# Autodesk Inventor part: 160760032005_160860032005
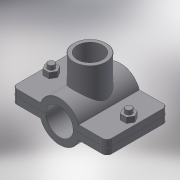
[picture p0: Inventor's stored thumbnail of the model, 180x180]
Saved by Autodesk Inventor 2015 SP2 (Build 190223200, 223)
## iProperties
Created: 2017-05
Part Number: 160760032005_160860032005
Material: Generic
Description: PLASSON SADDLE 32-1/2"
Document SubType Name: Modeling
Designer: KIM
Density: 1 g/cm^3
Appearance: Default
Author: KIM
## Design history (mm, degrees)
derived "16076.ipt"
feature "Solid1::16076.ipt"
feature "Solid2::16076.ipt"
tag "TaggingFeature1"
body "Solid1"
other parameters: "d0" = 48, "d1" = 92, "d2" = 16, "d3" = 32, "d5" = 0, "d6" = 4.6, "d7" = 92, "d8" = 0.1, "d10" = 0, "d11" = 0.32, "d14" = 24.2203, "d20" = 0.32, "d23" = 0.32, "d37" = 8, "d38" = 24, "d39" = 0, "d40" = 3, "d41" = 5, "d42" = 0, "d43" = 6, "d44" = 3, "d45" = 0, "d46" = 0.32, "d52" = 18.631, "d53" = 18, "d54" = 0, "d55" = 16, "d57" = 0, "d58" = 34.56, "d60" = 0, "d66" = 0, "d_" = 32, "B_" = 16, "G_" = 18.631, "L_" = 92, "l_2" = 18
